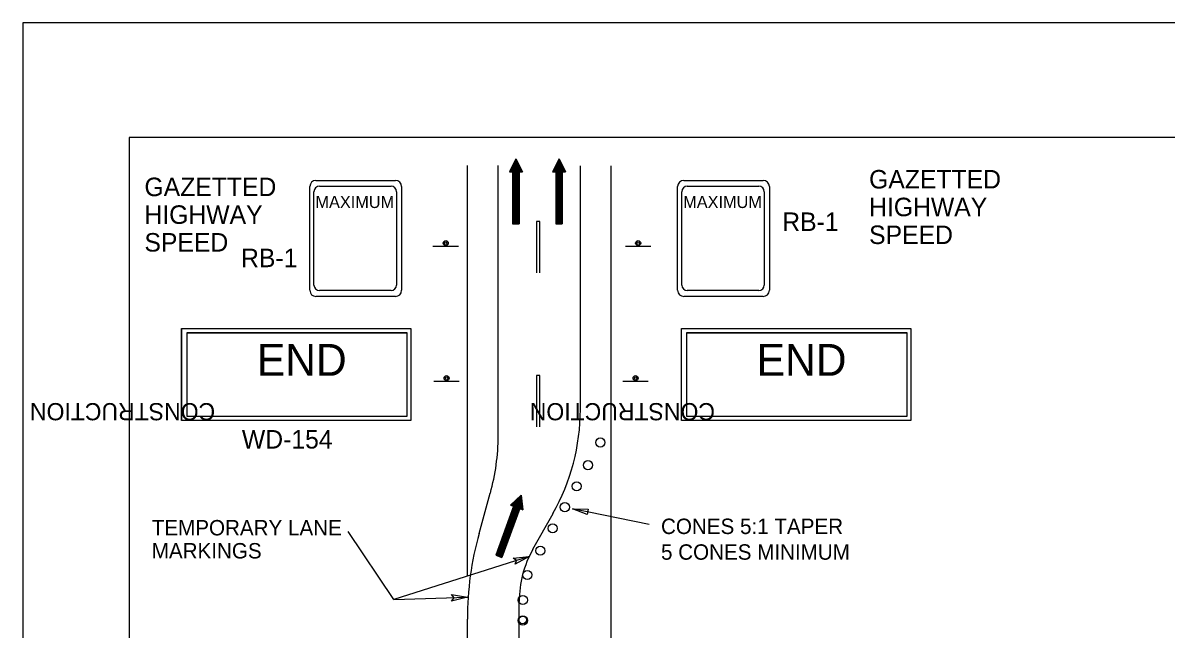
# Model space of a CAD drawing. Extents: x 2179 to 2395, y 134 to 413.
# Drawn here: x 2178.7 to 2286.4, y 355.7 to 412.8 of the extents above; entities that cross this region are included whole.
import ezdxf

# ---------------------------------------------------------------- set-up
doc = ezdxf.new("R2010")
doc.units = 0
for name, color, linetype in [('Level 1', 7, 'Continuous'), ('Level 10', 7, 'Continuous'), ('Level 2', 7, 'Continuous'), ('Level 44', 7, 'Continuous'), ('Level 5', 7, 'Continuous')]:
    doc.layers.add(name, color=color, linetype=linetype)

# ---------------------------------------------------------------- blocks, each defined once
blk = doc.blocks.new('LT1')
at = {"layer": 'Level 5'}
blk.add_lwpolyline([(0, 0), (-3, -0.62), (-2.504, 0), (-3, 0.62)], close=True, dxfattribs=at)
blk = doc.blocks.new('END')
at = {"layer": 'Level 2'}
for points in [[(0, 8.676), (21.598, 8.676), (21.598, 0), (0, 0)], [(0.511, 8.287), (21.224, 8.287), (21.224, 0.397), (0.511, 0.397)]]:
    blk.add_lwpolyline(points, close=True, dxfattribs=at)
at = {"layer": 'Level 44'}
for s, height, rotation, p in [('END', 3, 359.99999, (7.085, 4.219)), ('CONSTRUCTION', 1.62, 179.99999, (3.164, 1.653))]:
    blk.add_text(s, height=height, rotation=rotation, dxfattribs=at).set_placement(p)

msp = doc.modelspace()

# ---------------------------------------------------------------- linework, layer by layer
at = {"layer": 'Level 1'}
for p, q in [((2227.14, 394.06), (2227.14, 389.22)), ((2227.43, 394.06), (2227.14, 394.06)), ((2227.14, 394.06), (2227.14, 389.22)), ((2227.43, 394.06), (2227.14, 394.06)), ((2227.43, 389.22), (2227.43, 394.06)), ((2227.43, 389.22), (2227.43, 394.06)), ((2227.14, 379.54), (2227.14, 374.71)), ((2227.43, 379.54), (2227.14, 379.54)), ((2227.14, 379.54), (2227.14, 374.71)), ((2227.43, 379.54), (2227.14, 379.54)), ((2227.43, 374.71), (2227.43, 379.54)), ((2227.43, 374.71), (2227.43, 379.54))]:
    msp.add_line(p, q, dxfattribs=at)
for points in [[(2394.75, 412.76), (2178.75, 412.76), (2178.75, 133.76), (2394.75, 133.76)], [(2375.62, 401.95), (2188.75, 401.95), (2188.75, 144.57), (2375.62, 144.57)]]:
    msp.add_lwpolyline(points, close=True, dxfattribs=at)
at = {"layer": 'Level 10'}
for p, q in [((2225.19, 399.95), (2224.58, 398.72)), ((2225.04, 399.64), (2225.04, 393.82)), ((2225.11, 399.8), (2225.11, 393.82)), ((2225.19, 399.95), (2225.19, 393.82)), ((2225.19, 399.95), (2225.8, 398.72)), ((2225.27, 399.8), (2225.27, 393.82)), ((2225.34, 399.64), (2225.34, 393.82)), ((2229.26, 399.95), (2228.64, 398.72)), ((2229.1, 399.64), (2229.1, 393.82)), ((2229.18, 399.8), (2229.18, 393.82)), ((2229.26, 399.95), (2229.26, 393.82)), ((2229.26, 399.95), (2229.87, 398.72)), ((2229.33, 399.8), (2229.33, 393.82)), ((2229.41, 399.64), (2229.41, 393.82)), ((2220.62, 360.72), (2220.62, 399.31)), ((2223.52, 373.85), (2223.52, 399.31)), ((2224.58, 398.72), (2224.88, 398.72)), ((2224.65, 398.88), (2224.65, 398.72)), ((2224.73, 399.03), (2224.73, 398.72)), ((2224.81, 399.18), (2224.81, 398.72)), ((2224.88, 399.34), (2224.88, 393.82)), ((2224.88, 398.72), (2224.88, 393.82)), ((2224.96, 399.49), (2224.96, 393.82)), ((2225.42, 399.49), (2225.42, 393.82)), ((2225.5, 399.34), (2225.5, 393.82)), ((2225.5, 398.72), (2225.5, 393.82)), ((2225.5, 398.72), (2225.8, 398.72)), ((2225.57, 399.18), (2225.57, 398.72)), ((2225.65, 399.03), (2225.65, 398.72)), ((2225.73, 398.88), (2225.73, 398.72)), ((2228.64, 398.72), (2228.95, 398.72)), ((2228.72, 398.88), (2228.72, 398.72)), ((2228.8, 399.03), (2228.8, 398.72)), ((2228.87, 399.18), (2228.87, 398.72)), ((2228.95, 399.34), (2228.95, 393.82)), ((2228.95, 398.72), (2228.95, 393.82)), ((2229.03, 399.49), (2229.03, 393.82)), ((2229.49, 399.49), (2229.49, 393.82)), ((2229.56, 399.34), (2229.56, 393.82)), ((2229.56, 398.72), (2229.56, 393.82)), ((2229.56, 398.72), (2229.87, 398.72)), ((2229.64, 399.18), (2229.64, 398.72)), ((2229.72, 399.03), (2229.72, 398.72)), ((2229.79, 398.88), (2229.79, 398.72)), ((2231.26, 376.36), (2231.26, 399.28)), ((2234.16, 325.44), (2234.16, 399.28)), ((2224.88, 393.82), (2225.5, 393.82)), ((2228.95, 393.82), (2229.56, 393.82)), ((2221.72, 364.68), (2222.78, 368.47)), ((2225.19, 367.8), (2223.3, 362.62)), ((2225.31, 367.92), (2223.37, 362.59)), ((2225.43, 368.04), (2223.44, 362.56)), ((2225.56, 368.16), (2223.51, 362.54)), ((2225.68, 368.28), (2223.58, 362.51)), ((2225.7, 368.11), (2223.66, 362.48)), ((2225.72, 367.93), (2223.73, 362.46)), ((2225.74, 367.76), (2223.8, 362.43)), ((2225.76, 367.59), (2223.87, 362.41)), ((2225.68, 368.28), (2224.69, 367.33)), ((2224.69, 367.33), (2224.98, 367.23)), ((2224.81, 367.45), (2224.76, 367.31)), ((2224.94, 367.57), (2224.83, 367.28)), ((2225.06, 367.69), (2224.9, 367.25)), ((2225.78, 367.42), (2225.62, 366.99)), ((2225.68, 368.28), (2225.84, 366.91)), ((2225.8, 367.25), (2225.7, 366.96)), ((2224.98, 367.23), (2223.3, 362.62)), ((2225.55, 367.02), (2223.87, 362.41)), ((2225.55, 367.02), (2225.84, 366.91)), ((2225.82, 367.08), (2225.77, 366.94)), ((2226.79, 363.18), (2228.69, 366.54)), ((2237.75, 365.53), (2230.53, 367)), ((2213.68, 358.45), (2209.38, 364.85)), ((2226.45, 362.52), (2213.68, 358.45)), ((2223.3, 362.62), (2223.87, 362.41)), ((2213.68, 358.45), (2220.62, 358.66)), ((2225.5, 313.53), (2225.5, 358.27)), ((2220.62, 353.23), (2220.62, 356.61))]:
    msp.add_line(p, q, dxfattribs=at)
msp.add_lwpolyline([(2231.9, 366.46), (2230.53, 367), (2232.01, 366.95)], close=True, dxfattribs=at)
for centre, radius in [((2233.14, 373.24), 0.431), ((2231.98, 371.11), 0.431), ((2230.91, 369.12), 0.431), ((2229.8, 367.15), 0.431), ((2228.66, 365.15), 0.431), ((2227.5, 363.05), 0.431), ((2226.27, 360.77), 0.431), ((2225.84, 358.4), 0.431), ((2225.84, 356.48), 0.431), ((2225.84, 356.53), 0.359)]:
    msp.add_circle(centre, radius, dxfattribs=at)
for centre, radius, start, end in [((2211.26, 376.36), 20, 330.6023, 0), ((2203.52, 373.85), 20, 344.3937, 0), ((2250.62, 356.61), 30, 164.3937, 180), ((2235.5, 358.27), 10, 150.6023, 180)]:
    msp.add_arc(centre, radius, start, end, dxfattribs=at)
at = {"layer": 'Level 2'}
for points in [[(2193.71, 383.97), (2215.3, 383.97), (2215.3, 375.3), (2193.71, 375.3)], [(2194.22, 383.58), (2214.93, 383.58), (2214.93, 375.69), (2194.22, 375.69)], [(2240.78, 383.97), (2262.38, 383.97), (2262.38, 375.3), (2240.78, 375.3)], [(2241.29, 383.58), (2262, 383.58), (2262, 375.69), (2241.29, 375.69)]]:
    msp.add_lwpolyline(points, close=True, dxfattribs=at)
at = {"layer": 'Level 44'}
for p, q in [((2206.36, 397.92), (2213.85, 397.92)), ((2241, 397.92), (2248.49, 397.92)), ((2205.78, 387.57), (2205.78, 397.34)), ((2206.17, 388.07), (2206.17, 396.86)), ((2206.69, 397.38), (2213.43, 397.38)), ((2213.95, 396.86), (2213.95, 388.07)), ((2214.43, 397.34), (2214.43, 387.57)), ((2240.42, 387.57), (2240.42, 397.34)), ((2240.81, 388.07), (2240.81, 396.86)), ((2241.33, 397.38), (2248.07, 397.38)), ((2248.59, 396.86), (2248.59, 388.07)), ((2249.07, 397.34), (2249.07, 387.57)), ((2217.37, 391.74), (2219.77, 391.74)), ((2235.51, 391.74), (2237.91, 391.74)), ((2206.17, 388.07), (2206.17, 388.07)), ((2240.81, 388.07), (2240.81, 388.07)), ((2205.78, 387.57), (2205.78, 387.57)), ((2213.85, 386.99), (2206.36, 386.99)), ((2213.43, 387.55), (2206.69, 387.55)), ((2240.42, 387.57), (2240.42, 387.57)), ((2248.49, 386.99), (2241, 386.99)), ((2248.07, 387.55), (2241.33, 387.55)), ((2217.45, 379.03), (2219.85, 379.03)), ((2235.27, 379.03), (2237.66, 379.03))]:
    msp.add_line(p, q, dxfattribs=at)
for centre, radius in [((2218.58, 392.01), 0.24), ((2218.58, 392.01), 0.12), ((2236.71, 392.01), 0.24), ((2236.71, 392.01), 0.12), ((2218.66, 379.3), 0.24), ((2218.66, 379.3), 0.12), ((2236.47, 379.3), 0.24), ((2236.47, 379.3), 0.12)]:
    msp.add_circle(centre, radius, dxfattribs=at)
for centre, radius, start, end in [((2206.36, 397.34), 0.578, 90, 180), ((2213.85, 397.34), 0.578, 360, 90), ((2241, 397.34), 0.578, 90, 180), ((2248.49, 397.34), 0.578, 360, 90), ((2206.69, 396.86), 0.52, 90, 180), ((2213.43, 396.86), 0.52, 360, 90), ((2241.33, 396.86), 0.52, 90, 180), ((2248.07, 396.86), 0.52, 360, 90), ((2206.69, 388.07), 0.52, 180, 270), ((2213.43, 388.07), 0.52, 270, 360), ((2241.33, 388.07), 0.52, 180, 270), ((2248.07, 388.07), 0.52, 270, 360), ((2206.36, 387.57), 0.578, 180, 270), ((2213.85, 387.57), 0.578, 270, 360), ((2241, 387.57), 0.578, 180, 270), ((2248.49, 387.57), 0.578, 270, 360)]:
    msp.add_arc(centre, radius, start, end, dxfattribs=at)

# ---------------------------------------------------------------- block references
at = {"layer": 'Level 2'}
for p in [(2193.7, 375.3), (2240.78, 375.3)]:
    msp.add_blockref('END', p, dxfattribs=at)
at = {"layer": 'Level 5', "xscale": 0.5}
for p, yscale, rotation in [((2226.45, 362.52), 0.5000000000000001, 17.68769606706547), ((2220.62, 358.66), 0.5, 1.7164611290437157)]:
    msp.add_blockref('LT1', p, dxfattribs=dict(at, yscale=yscale, rotation=rotation))

# ---------------------------------------------------------------- texts
at = {"layer": 'Level 10'}
for s, height, p in [('GAZETTED', 1.742, (2258.46, 397.16)), ('GAZETTED', 1.742, (2190.2, 396.44)), ('HIGHWAY', 1.742, (2258.46, 394.55)), ('HIGHWAY', 1.742, (2190.2, 393.83)), ('RB-1', 1.742, (2250.28, 393.16)), ('SPEED', 1.742, (2258.46, 391.93)), ('SPEED', 1.742, (2190.2, 391.22)), ('RB-1', 1.742, (2199.3, 389.75)), ('WD-154', 1.742, (2199.38, 372.67)), ('CONES 5:1 TAPER', 1.4514, (2238.86, 364.62)), ('5 CONES MINIMUM', 1.4514, (2238.86, 362.2))]:
    msp.add_text(s, height=height, dxfattribs=at).set_placement(p)
at = {"layer": 'Level 44'}
for p in [(2206.31, 395.32), (2240.95, 395.32)]:
    msp.add_text('MAXIMUM', height=1.147, rotation=360, dxfattribs=at).set_placement(p)
at = {"layer": 'Level 5'}
for s, height, p in [('TEMPORARY LANE', 1.4514, (2190.89, 364.49)), ('MARKINGS', 1.451, (2190.89, 362.32))]:
    msp.add_text(s, height=height, dxfattribs=at).set_placement(p)

doc.saveas('drawing.dxf')
